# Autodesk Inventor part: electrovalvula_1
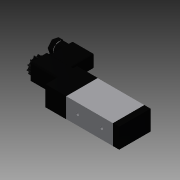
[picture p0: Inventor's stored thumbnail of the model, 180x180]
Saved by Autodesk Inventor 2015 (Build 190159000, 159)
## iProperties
Created: 2016-06
Part Number: electrovalvula_1
Material: Genérico
Document SubType Name: Modeling
Designer: Diego
Density: 1 g/cm^3
Appearance: Valor por defecto
Author: Diego
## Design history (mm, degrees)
sketch "Boceto1"
  geometry: L1 (0, 0)-(52, 0); L2 (52, 0)-(52, 35); L3 (52, 35)-(0, 35); L4 (0, 35)-(0, 0)
  constraints: 8 end point, 2 parallel, 1 horizontal, 1 perpendicular
  dimensions: "d0" = 52 distance of L3.end L2.end; "d1" = 35 distance of L2.end L1.end
extrude "Extrusión1" new body sketch "Boceto1" distance "d2" = 22; taper "d3" = 0 deg
sketch "Boceto2"
  geometry: L1 (0, 0)-(0, 35) reference; L2 (-22, 0)-(-22, 35) reference; L3 (0, 0)-(-22, 0) reference; L4 (0.01, 35.01)-(0.01, -0.01); L5 (0.01, -0.01)-(-22.01, -0.01); L6 (-22.01, -0.01)-(-22.01, 35.01); L7 (-22.01, 35.01)-(0.01, 35.01)
  constraints: 8 end point, 2 other
  dimensions: "d4" = 0.01 distance between parallel lines of L1 L4
extrude "Extrusión2" join sketch "Boceto2" distance "d5" = 7; taper "d6" = 0 deg
sketch "Boceto3"
  geometry: L1 (0, 35)-(0, 0) reference; L2 (0, 0)-(22, 0) reference; L3 (22, 35)-(22, 0) reference; L4 (0, 35)-(22, 35) reference; L5 (22.1, -0.1)-(-0.1, -0.1); L6 (-0.1, -0.1)-(-0.1, 35.1); L7 (-0.1, 35.1)-(22.1, 35.1); L8 (22.1, 35.1)-(22.1, -0.1); 1 further point
  constraints: 8 end point, 3 other
  dimensions: "d7" = 0.1 distance between parallel lines of L3 L8
extrude "Extrusión3" join sketch "Boceto3" distance "d8" = 23; taper "d9" = 0 deg
sketch "Boceto4"
  geometry: L1 (22.1, 35.1)-(-0.1, 35.1) reference; L2 (-0.1, -0.1)-(22.1, -0.1) reference; L3 (22.1, -0.1)-(22.1, 35.1) reference; L4 (22.1, 35.1)-(-0.1, 35.1) reference; L5 (-0.1, 35.1)-(-0.1, -0.1) reference; L6 (20.6, 33.6)-(1.4, 33.6); L7 (1.4, 33.6)-(20.6, 33.6); L8 (20.6, 33.6)-(20.6, 14.4); L9 (20.6, 14.4)-(1.4, 14.4); L10 (1.4, 14.4)-(1.4, 33.6); 1 further point
  constraints: 10 end point, 2 parallel, 1 horizontal, 1 perpendicular
  dimensions: "d12" = 19.2 distance of L7.end L8.end
extrude "Extrusión4" join sketch "Boceto4" distance "d13" = 31; taper "d14" = 0 deg
fillet "Empalme1" dims "d15" = 2
sketch "Boceto5"
  geometry: L1 (0, 15.2)-(-31, 15.2) reference; L2 (-31, 0)-(-6, 0); L3 (-6, 0)-(-6, 15.2); L4 (-6, 15.2)-(-31, 15.2); L5 (-31, 15.2)-(-31, 0); 1 further point
  constraints: 8 end point, 2 parallel, 1 horizontal, 1 perpendicular, 1 point on line
  dimensions: "d16" = 25 distance of L4.end L3.end
extrude "Extrusión5" join sketch "Boceto5" distance "d17" = 3; taper "d18" = 0 deg
sketch "Boceto6"
  geometry: L1 (-31, 0)-(-6, 0) reference; L2 (-31, 0)-(-6, 0) reference; L3 (-6, 0)-(-6, 15.2) reference; L4 (-6, 15.2)-(-31, 15.2) reference; L5 (-31, 15.2)-(-31, 0) reference; L6 (-30.5, 14.7)-(-6.5, 14.7); L7 (-6.5, 14.7)-(-6.5, 0.5); L8 (-6.5, 0.5)-(-30.5, 0.5); L9 (-30.5, 0.5)-(-30.5, 14.7); 1 further point
  constraints: 8 end point, 3 other
  dimensions: "d19" = 0.5 distance between parallel lines of L4 L6
extrude "Extrusión6" join sketch "Boceto6" distance "d20" = 24; taper "d21" = 0 deg
sketch "Boceto7"
  geometry: C1 r 9 at (11, 24); 1 further point
  constraints: 1 centre point
  dimensions: "d22" = 18 diameter of C1
extrude "Extrusión7" join sketch "Boceto7" distance "d23" = 5; taper "d24" = 0 deg
fillet "Empalme2" dims "d25" = 0.5
sketch "Boceto8"
  geometry: C1 r 6.926 at (7.1, -7.417); 1 further point
  constraints: 1 centre point
extrude "Extrusión8" join sketch "Boceto8" distance "d26" = 7; taper "d27" = 0 deg
sketch "Boceto9"
  geometry: C1 r 6.926 at (0, 0) reference; C2 r 6.426 at (0, 0); 1 further point
  constraints: 1 centre point
  dimensions: "d28" = 0.5 radial gap between concentric circles of C1 C2
extrude "Extrusión9" join sketch "Boceto9" distance "d29" = 1; taper "d30" = 0 deg
sketch "Boceto10"
  geometry: L1 (-6.959, 2.593)-(-1.235, 7.323); L2 (-1.235, 7.323)-(5.724, 4.731); L3 (5.724, 4.731)-(7.1, -2.566); L4 (7.1, -16.583)-(7.1, 7.417) reference; L5 (7.1, -2.566)-(1.377, -7.298); L6 (1.377, -7.298)-(-5.631, -4.841); L7 (-5.631, -4.841)-(-6.959, 2.593); 1 further point
  constraints: 12 end point, 1 point on line
  dimensions: "d33" = 7.426 distance of L1.end L2.end; "d34" = 7.426 distance of L2.end L3.end; "d35" = 7.426 distance of L3.end L5.end; "d36" = 7.426 distance of L5.end L6.end
extrude "Extrusión10" join sketch "Boceto10" distance "d37" = 5; taper "d38" = 0 deg
fillet "Empalme3" dims "d39" = 1
sketch "Boceto11"
  geometry: 14 further points
  constraints: 15 other
  dimensions: "d42" = 360 deg dimension on point (0, 0) point (-8.436, 3.136) (derived)
hole "Agujero1" sketch "Boceto11" at (-8.436, 3.136), (-8.874, -1.503), (-6.934, -5.738), (-3.136, -8.436), (1.503, -8.874), (5.738, -6.934), (8.436, -3.136), (8.874, 1.503), (6.934, 5.738), (3.136, 8.436), (-1.503, 8.874), (-5.738, 6.934) diameter "d44" = 4; stored, may be unused: countersink angle "d48" = 90 deg, drill point angle "d50" = 0 deg; dims "d45" = 6, "d46" = 4, "d47" = 2, "d49" = 5
sketch "Boceto12"
  geometry: C1 r 2 at (-18.327, 11.1); 1 further point
  constraints: 1 centre point
  dimensions: "d51" = 4 diameter of C1
extrude "Extrusión11" join sketch "Boceto12" distance "d52" = 5; taper "d53" = 0 deg
sketch "Boceto13"
  geometry: L1 (0, 2.5)-(7.548, 1.47); L2 (18.327, 11.1)-(18.327, -11.1) reference; L3 (0, -2.5)-(7.548, -1.47); A1 r 2.5 centre (0, 0) between (0.67, 2.409) and (0.67, -2.409); A2 r 1.508 centre (7.215, 0) between (7.358, -1.501) and (7.287, 1.506); 1 further point
  constraints: 8 point on circle, 4 end point, 3 point on line, 2 centre point
extrude "Extrusión12" join sketch "Boceto13" distance "d55" = 2; taper "d56" = 0 deg
sketch "Boceto19"
  geometry: 2 further points
hole "Agujero2" sketch "Boceto19" at (-26, 11) diameter "d102" = 3; stored, may be unused: countersink angle "d106" = 90 deg, drill point angle "d108" = 118 deg; dims "d103" = 6, "d104" = 4, "d105" = 2, "d107" = 1
sketch "Boceto20"
  geometry: L1 (-52, 0)-(-52, 22) reference; L2 (0, 0)-(0, 22) reference; 2 further points
hole "Agujero3" sketch "Boceto20" at (-39.419, 11), (-12.581, 11) diameter "d109" = 3; stored, may be unused: countersink angle "d113" = 90 deg, drill point angle "d115" = 118 deg; dims "d110" = 6, "d111" = 4, "d112" = 2, "d114" = 1
node "Sólido1"
node "Contorno proyectado1"
node "Contorno proyectado2"
node "Contorno proyectado3"
node "Contorno proyectado4"
